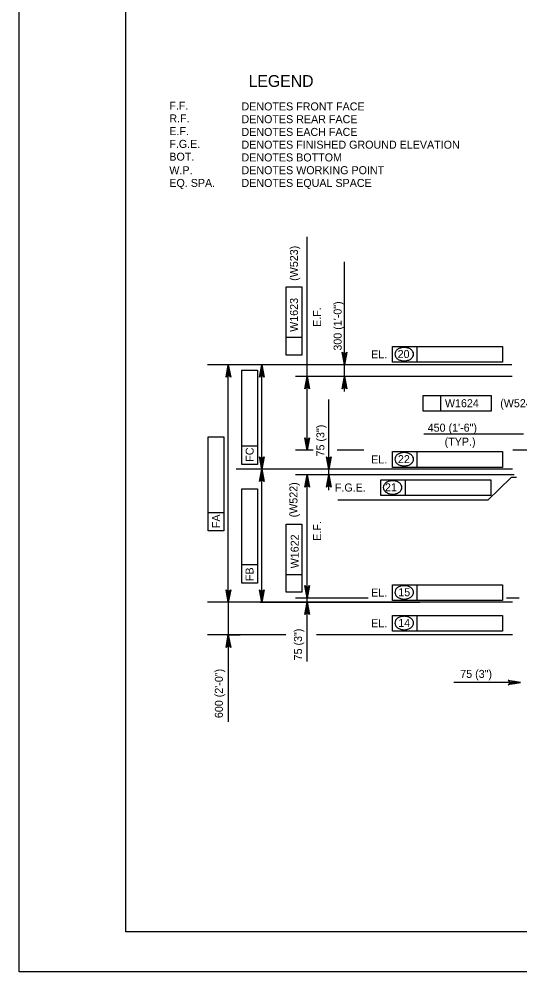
# Model space of a CAD drawing. Extents: x 634540 to 640306, y 296059 to 300275.
# Drawn here: x 638435.5 to 638623.2, y 296059.5 to 296416.6 of the extents above; entities that cross this region are included whole.
import ezdxf

# ---------------------------------------------------------------- set-up
doc = ezdxf.new("R2010")
doc.units = 0
for name, color, linetype in [('2', 7, 'Continuous'), ('3', 7, 'Continuous'), ('4', 7, 'Continuous'), ('PLT-BNDY', 7, 'Continuous')]:
    doc.layers.add(name, color=color, linetype=linetype)

msp = doc.modelspace()

# ---------------------------------------------------------------- linework, layer by layer
at = {"layer": '2'}
for p, q in [((638475.46, 296074.46), (638475.46, 296638.46)), ((639261.46, 296074.46), (638475.46, 296074.46))]:
    msp.add_line(p, q, dxfattribs=at)
at = {"layer": '3'}
for p, q in [((638624.51, 296260.98), (638587.22, 296260.98)), ((638621.91, 296244.82), (638619.95, 296244.82))]:
    msp.add_line(p, q, dxfattribs=at)
at = {"layer": '4'}
for p, q in [((638543.46, 296257.92), (638543.46, 296335.02)), ((638557.42, 296276.97), (638557.42, 296325.64)), ((638535.57, 296290.66), (638535.57, 296316.19)), ((638535.57, 296316.19), (638541.48, 296316.19)), ((638541.48, 296316.19), (638541.48, 296290.66)), ((638541.48, 296297.25), (638535.57, 296297.25)), ((638575.44, 296293.83), (638616.65, 296293.83)), ((638575.44, 296287.93), (638575.44, 296293.83)), ((638584.61, 296287.93), (638584.61, 296293.83)), ((638616.65, 296293.83), (638616.65, 296287.93)), ((638541.48, 296290.66), (638535.57, 296290.66)), ((638620.17, 296287.02), (638506.06, 296287.02)), ((638521.43, 296287.02), (638509.46, 296287.02)), ((638585.87, 296287.02), (638522.01, 296287.02)), ((638616.65, 296287.93), (638575.44, 296287.93)), ((638513.89, 296201.02), (638513.89, 296284.07)), ((638518.91, 296249.64), (638518.91, 296284.95)), ((638518.91, 296284.95), (638524.81, 296284.95)), ((638524.81, 296284.95), (638524.81, 296249.64)), ((638526.44, 296250.85), (638526.44, 296284.07)), ((638620.29, 296282.65), (638539.03, 296282.65)), ((638586.92, 296275.52), (638612.46, 296275.52)), ((638586.92, 296269.61), (638586.92, 296275.52)), ((638593.51, 296269.61), (638593.51, 296275.52)), ((638612.46, 296275.52), (638612.46, 296269.61)), ((638551.53, 296240.06), (638551.53, 296273.97)), ((638612.46, 296269.61), (638586.92, 296269.61)), ((638506.36, 296224.73), (638506.36, 296260.03)), ((638506.36, 296260.03), (638512.27, 296260.03)), ((638512.27, 296260.03), (638512.27, 296224.73)), ((638524.81, 296256.49), (638518.91, 296256.49)), ((638545.67, 296254.97), (638539.03, 296254.97)), ((638564.74, 296254.97), (638554.72, 296254.97)), ((638575.44, 296254.45), (638616.65, 296254.45)), ((638575.44, 296248.54), (638575.44, 296254.45)), ((638584.61, 296248.54), (638584.61, 296254.45)), ((638616.65, 296254.45), (638616.65, 296248.54)), ((638636.58, 296254.97), (638620.55, 296254.97)), ((638620.46, 296247.9), (638516.83, 296247.9)), ((638524.81, 296249.64), (638518.91, 296249.64)), ((638592.28, 296247.9), (638522.01, 296247.9)), ((638585.87, 296247.9), (638522.01, 296247.9)), ((638616.65, 296248.54), (638575.44, 296248.54)), ((638526.44, 296201.02), (638526.44, 296244.94)), ((638621.06, 296245.74), (638539.03, 296245.74)), ((638571.09, 296243.88), (638612.3, 296243.88)), ((638571.09, 296237.97), (638571.09, 296243.88)), ((638580.26, 296237.97), (638580.26, 296243.88)), ((638619.95, 296244.82), (638611.11, 296236.3)), ((638612.3, 296243.88), (638612.3, 296237.97)), ((638518.91, 296205.17), (638518.91, 296240.47)), ((638518.91, 296240.47), (638524.81, 296240.47)), ((638524.81, 296240.47), (638524.81, 296205.17)), ((638543.46, 296198.06), (638543.46, 296242.79)), ((638611.11, 296236.3), (638554.98, 296236.3)), ((638612.3, 296237.97), (638571.09, 296237.97)), ((638512.27, 296231.57), (638506.36, 296231.57)), ((638535.57, 296201.75), (638535.57, 296227.28)), ((638535.57, 296227.28), (638541.48, 296227.28)), ((638541.48, 296227.28), (638541.48, 296201.75)), ((638512.27, 296224.73), (638506.36, 296224.73)), ((638524.81, 296212.01), (638518.91, 296212.01)), ((638541.48, 296208.34), (638535.57, 296208.34)), ((638524.81, 296205.17), (638518.91, 296205.17)), ((638575.44, 296204.56), (638616.65, 296204.56)), ((638575.44, 296198.65), (638575.44, 296204.56)), ((638584.61, 296198.65), (638584.61, 296204.56)), ((638616.65, 296204.56), (638616.65, 296198.65)), ((638541.48, 296201.75), (638535.57, 296201.75)), ((638620.46, 296198.06), (638506.06, 296198.06)), ((638521.43, 296198.06), (638509.46, 296198.06)), ((638513.89, 296198.06), (638513.89, 296185.76)), ((638592.28, 296198.06), (638522.01, 296198.06)), ((638525.84, 296198.06), (638585.7, 296198.06)), ((638566.35, 296199.6), (638539.03, 296199.6)), ((638616.65, 296198.65), (638575.44, 296198.65)), ((638622.94, 296199.6), (638618.16, 296199.6)), ((638543.46, 296175.86), (638543.46, 296195.11)), ((638575.44, 296193.07), (638616.65, 296193.07)), ((638575.44, 296187.17), (638575.44, 296193.07)), ((638584.61, 296187.17), (638584.61, 296193.07)), ((638616.65, 296193.07), (638616.65, 296187.17)), ((638616.65, 296187.17), (638575.44, 296187.17)), ((638535.5, 296185.76), (638506.06, 296185.76)), ((638513.29, 296185.76), (638518.32, 296185.76)), ((638513.89, 296182.81), (638513.89, 296153.14)), ((638620.46, 296185.76), (638546.92, 296185.76)), ((638617.54, 296167.92), (638598.47, 296167.92)), ((638620.49, 296167.92), (638617.54, 296167.92))]:
    msp.add_line(p, q, dxfattribs=at)
for points in [[(638557.42, 296287.02), (638556.55, 296291.68), (638556.8, 296291.32), (638557.11, 296291.14), (638557.42, 296291.08), (638557.74, 296291.14), (638558.05, 296291.32), (638558.3, 296291.68), (638557.42, 296287.02), (638558.05, 296291.32), (638557.74, 296291.14), (638557.42, 296287.02), (638557.42, 296291.08), (638557.11, 296291.14), (638557.42, 296287.02), (638556.8, 296291.32)], [(638513.89, 296287.02), (638514.77, 296282.36), (638514.52, 296282.72), (638514.21, 296282.9), (638513.89, 296282.96), (638513.58, 296282.9), (638513.27, 296282.72), (638513.02, 296282.36), (638513.89, 296287.02), (638513.27, 296282.72), (638513.58, 296282.9), (638513.89, 296287.02), (638513.89, 296282.96), (638514.21, 296282.9), (638513.89, 296287.02), (638514.52, 296282.72)], [(638526.44, 296287.02), (638527.31, 296282.36), (638527.07, 296282.72), (638526.75, 296282.9), (638526.44, 296282.96), (638526.13, 296282.9), (638525.82, 296282.72), (638525.57, 296282.36), (638526.44, 296287.02), (638525.82, 296282.72), (638526.13, 296282.9), (638526.44, 296287.02), (638526.44, 296282.96), (638526.75, 296282.9), (638526.44, 296287.02), (638527.07, 296282.72)], [(638543.46, 296282.65), (638544.33, 296277.99), (638544.09, 296278.35), (638543.77, 296278.54), (638543.46, 296278.59), (638543.15, 296278.54), (638542.84, 296278.35), (638542.59, 296277.99), (638543.46, 296282.65), (638542.84, 296278.35), (638543.15, 296278.54), (638543.46, 296282.65), (638543.46, 296278.59), (638543.77, 296278.54), (638543.46, 296282.65), (638544.09, 296278.35)], [(638557.42, 296282.65), (638558.3, 296277.99), (638558.05, 296278.35), (638557.74, 296278.54), (638557.42, 296278.59), (638557.11, 296278.54), (638556.8, 296278.35), (638556.55, 296277.99), (638557.42, 296282.65), (638556.8, 296278.35), (638557.11, 296278.54), (638557.42, 296282.65), (638557.42, 296278.59), (638557.74, 296278.54), (638557.42, 296282.65), (638558.05, 296278.35)], [(638543.46, 296254.97), (638542.59, 296259.63), (638542.84, 296259.27), (638543.15, 296259.09), (638543.46, 296259.03), (638543.77, 296259.09), (638544.09, 296259.27), (638544.33, 296259.63), (638543.46, 296254.97), (638544.09, 296259.27), (638543.77, 296259.09), (638543.46, 296254.97), (638543.46, 296259.03), (638543.15, 296259.09), (638543.46, 296254.97), (638542.84, 296259.27)], [(638526.44, 296247.9), (638525.57, 296252.56), (638525.82, 296252.2), (638526.13, 296252.01), (638526.44, 296251.96), (638526.75, 296252.01), (638527.07, 296252.2), (638527.31, 296252.56), (638526.44, 296247.9), (638527.07, 296252.2), (638526.75, 296252.01), (638526.44, 296247.9), (638526.44, 296251.96), (638526.13, 296252.01), (638526.44, 296247.9), (638525.82, 296252.2)], [(638551.53, 296247.9), (638550.66, 296252.56), (638550.91, 296252.2), (638551.22, 296252.01), (638551.53, 296251.96), (638551.85, 296252.01), (638552.16, 296252.2), (638552.41, 296252.56), (638551.53, 296247.9), (638552.16, 296252.2), (638551.85, 296252.01), (638551.53, 296247.9), (638551.53, 296251.96), (638551.22, 296252.01), (638551.53, 296247.9), (638550.91, 296252.2)], [(638526.44, 296247.9), (638527.31, 296243.23), (638527.07, 296243.59), (638526.75, 296243.78), (638526.44, 296243.83), (638526.13, 296243.78), (638525.82, 296243.59), (638525.57, 296243.23), (638526.44, 296247.9), (638525.82, 296243.59), (638526.13, 296243.78), (638526.44, 296247.9), (638526.44, 296243.83), (638526.75, 296243.78), (638526.44, 296247.9), (638527.07, 296243.59)], [(638543.46, 296245.74), (638544.33, 296241.08), (638544.09, 296241.44), (638543.77, 296241.62), (638543.46, 296241.68), (638543.15, 296241.62), (638542.84, 296241.44), (638542.59, 296241.08), (638543.46, 296245.74), (638542.84, 296241.44), (638543.15, 296241.62), (638543.46, 296245.74), (638543.46, 296241.68), (638543.77, 296241.62), (638543.46, 296245.74), (638544.09, 296241.44)], [(638551.53, 296245.74), (638552.41, 296241.08), (638552.16, 296241.44), (638551.85, 296241.62), (638551.53, 296241.68), (638551.22, 296241.62), (638550.91, 296241.44), (638550.66, 296241.08), (638551.53, 296245.74), (638550.91, 296241.44), (638551.22, 296241.62), (638551.53, 296245.74), (638551.53, 296241.68), (638551.85, 296241.62), (638551.53, 296245.74), (638552.16, 296241.44)], [(638543.46, 296199.6), (638542.59, 296204.26), (638542.84, 296203.91), (638543.15, 296203.72), (638543.46, 296203.67), (638543.77, 296203.72), (638544.09, 296203.91), (638544.33, 296204.26), (638543.46, 296199.6), (638544.09, 296203.91), (638543.77, 296203.72), (638543.46, 296199.6), (638543.46, 296203.67), (638543.15, 296203.72), (638543.46, 296199.6), (638542.84, 296203.91)], [(638513.89, 296198.06), (638513.02, 296202.72), (638513.27, 296202.37), (638513.58, 296202.18), (638513.89, 296202.13), (638514.21, 296202.18), (638514.52, 296202.37), (638514.77, 296202.72), (638513.89, 296198.06), (638514.52, 296202.37), (638514.21, 296202.18), (638513.89, 296198.06), (638513.89, 296202.13), (638513.58, 296202.18), (638513.89, 296198.06), (638513.27, 296202.37)], [(638526.44, 296198.06), (638525.57, 296202.72), (638525.82, 296202.37), (638526.13, 296202.18), (638526.44, 296202.13), (638526.75, 296202.18), (638527.07, 296202.37), (638527.31, 296202.72), (638526.44, 296198.06), (638527.07, 296202.37), (638526.75, 296202.18), (638526.44, 296198.06), (638526.44, 296202.13), (638526.13, 296202.18), (638526.44, 296198.06), (638525.82, 296202.37)], [(638543.46, 296198.06), (638544.33, 296193.4), (638544.09, 296193.76), (638543.77, 296193.95), (638543.46, 296194), (638543.15, 296193.95), (638542.84, 296193.76), (638542.59, 296193.4), (638543.46, 296198.06), (638542.84, 296193.76), (638543.15, 296193.95), (638543.46, 296198.06), (638543.46, 296194), (638543.77, 296193.95), (638543.46, 296198.06), (638544.09, 296193.76)], [(638513.89, 296185.76), (638514.77, 296181.1), (638514.52, 296181.46), (638514.21, 296181.64), (638513.89, 296181.7), (638513.58, 296181.64), (638513.27, 296181.46), (638513.02, 296181.1), (638513.89, 296185.76), (638513.27, 296181.46), (638513.58, 296181.64), (638513.89, 296185.76), (638513.89, 296181.7), (638514.21, 296181.64), (638513.89, 296185.76), (638514.52, 296181.46)], [(638623.45, 296167.92), (638618.79, 296167.04), (638619.15, 296167.29), (638619.33, 296167.6), (638619.39, 296167.92), (638619.33, 296168.23), (638619.15, 296168.54), (638618.79, 296168.79), (638623.45, 296167.92), (638619.15, 296168.54), (638619.33, 296168.23), (638623.45, 296167.92), (638619.39, 296167.92), (638619.33, 296167.6), (638623.45, 296167.92), (638619.15, 296167.29)]]:
    msp.add_lwpolyline(points, dxfattribs=at)
for points in [[(638556.93, 296289.97), (638557.92, 296289.97), (638557.42, 296287.02)], [(638513.4, 296284.07), (638514.38, 296284.07), (638513.89, 296287.02)], [(638525.95, 296284.07), (638526.93, 296284.07), (638526.44, 296287.02)], [(638542.97, 296279.7), (638543.95, 296279.7), (638543.46, 296282.65)], [(638556.93, 296279.7), (638557.92, 296279.7), (638557.42, 296282.65)], [(638542.97, 296257.92), (638543.95, 296257.92), (638543.46, 296254.97)], [(638525.95, 296250.85), (638526.93, 296250.85), (638526.44, 296247.9)], [(638551.04, 296250.85), (638552.03, 296250.85), (638551.53, 296247.9)], [(638525.95, 296244.94), (638526.93, 296244.94), (638526.44, 296247.9)], [(638542.97, 296242.79), (638543.95, 296242.79), (638543.46, 296245.74)], [(638551.04, 296242.79), (638552.03, 296242.79), (638551.53, 296245.74)], [(638513.4, 296201.02), (638514.38, 296201.02), (638513.89, 296198.06)], [(638525.95, 296201.02), (638526.93, 296201.02), (638526.44, 296198.06)], [(638542.97, 296202.56), (638543.95, 296202.56), (638543.46, 296199.6)], [(638542.97, 296195.11), (638543.95, 296195.11), (638543.46, 296198.06)], [(638513.4, 296182.81), (638514.38, 296182.81), (638513.89, 296185.76)], [(638620.49, 296168.41), (638620.49, 296167.42), (638623.45, 296167.92)]]:
    msp.add_lwpolyline(points, close=True, dxfattribs=at)
for centre, radius, start, end in [((638579.47, 296289.79), 3.66, 106.5358, 125.6316), ((638579.81, 296288.63), 4.87, 90, 106.5358), ((638579.81, 296288.63), 4.87, 73.4642, 90), ((638580.16, 296289.79), 3.66, 54.3684, 73.4642), ((638578.14, 296290.99), 1.83, 149.9767, 180), ((638578.14, 296290.99), 1.83, 180, 210.0233), ((638578.94, 296290.52), 2.76, 125.6316, 149.9767), ((638578.94, 296291.45), 2.76, 210.0233, 234.3684), ((638580.68, 296290.52), 2.76, 30.0233, 54.3684), ((638580.68, 296291.45), 2.76, 305.6316, 329.9767), ((638581.49, 296290.99), 1.83, 0, 30.0233), ((638581.49, 296290.99), 1.83, 329.9767, 0), ((638579.47, 296292.19), 3.66, 234.3684, 253.4642), ((638579.81, 296293.35), 4.87, 253.4642, 270), ((638579.81, 296293.35), 4.87, 270, 286.5358), ((638580.16, 296292.19), 3.66, 286.5358, 305.6316), ((638579.47, 296250.4), 3.66, 106.5358, 125.6316), ((638579.81, 296249.24), 4.87, 90, 106.5358), ((638579.81, 296249.24), 4.87, 73.4642, 90), ((638580.16, 296250.4), 3.66, 54.3684, 73.4642), ((638578.14, 296251.6), 1.83, 149.9767, 180), ((638578.14, 296251.6), 1.83, 180, 210.0233), ((638578.94, 296251.14), 2.76, 125.6316, 149.9767), ((638578.94, 296252.07), 2.76, 210.0233, 234.3684), ((638580.68, 296251.14), 2.76, 30.0233, 54.3684), ((638580.68, 296252.07), 2.76, 305.6316, 329.9767), ((638581.49, 296251.6), 1.83, 0, 30.0233), ((638581.49, 296251.6), 1.83, 329.9767, 0), ((638579.47, 296252.8), 3.66, 234.3684, 253.4642), ((638579.81, 296253.96), 4.87, 253.4642, 270), ((638579.81, 296253.96), 4.87, 270, 286.5358), ((638580.16, 296252.8), 3.66, 286.5358, 305.6316), ((638575.12, 296239.83), 3.66, 106.5358, 125.6316), ((638575.47, 296238.67), 4.87, 90, 106.5358), ((638575.47, 296238.67), 4.87, 73.4642, 90), ((638575.81, 296239.83), 3.66, 54.3684, 73.4642), ((638573.79, 296241.03), 1.83, 149.9767, 180), ((638573.79, 296241.03), 1.83, 180, 210.0233), ((638574.6, 296240.57), 2.76, 125.6316, 149.9767), ((638574.6, 296241.5), 2.76, 210.0233, 234.3684), ((638576.34, 296240.57), 2.76, 30.0233, 54.3684), ((638576.34, 296241.5), 2.76, 305.6316, 329.9767), ((638577.14, 296241.03), 1.83, 0, 30.0233), ((638577.14, 296241.03), 1.83, 329.9767, 0), ((638575.12, 296242.24), 3.66, 234.3684, 253.4642), ((638575.47, 296243.4), 4.87, 253.4642, 270), ((638575.47, 296243.4), 4.87, 270, 286.5358), ((638575.81, 296242.24), 3.66, 286.5358, 305.6316), ((638579.47, 296200.51), 3.66, 106.5358, 125.6316), ((638579.81, 296199.35), 4.87, 90, 106.5358), ((638579.81, 296199.35), 4.87, 73.4642, 90), ((638580.16, 296200.51), 3.66, 54.3684, 73.4642), ((638578.14, 296201.71), 1.83, 149.9767, 180), ((638578.14, 296201.71), 1.83, 180, 210.0233), ((638578.94, 296201.25), 2.76, 125.6316, 149.9767), ((638578.94, 296202.18), 2.76, 210.0233, 234.3684), ((638580.68, 296201.25), 2.76, 30.0233, 54.3684), ((638580.68, 296202.18), 2.76, 305.6316, 329.9767), ((638581.49, 296201.71), 1.83, 0, 30.0233), ((638581.49, 296201.71), 1.83, 329.9767, 0), ((638579.47, 296202.91), 3.66, 234.3684, 253.4642), ((638579.81, 296204.07), 4.87, 253.4642, 270), ((638579.81, 296204.07), 4.87, 270, 286.5358), ((638580.16, 296202.91), 3.66, 286.5358, 305.6316), ((638578.14, 296190.23), 1.83, 149.9767, 180), ((638578.14, 296190.23), 1.83, 180, 210.0233), ((638578.94, 296189.76), 2.76, 125.6316, 149.9767), ((638579.47, 296189.03), 3.66, 106.5358, 125.6316), ((638579.81, 296187.87), 4.87, 90, 106.5358), ((638579.81, 296187.87), 4.87, 73.4642, 90), ((638580.16, 296189.03), 3.66, 54.3684, 73.4642), ((638580.68, 296189.76), 2.76, 30.0233, 54.3684), ((638581.49, 296190.23), 1.83, 0, 30.0233), ((638581.49, 296190.23), 1.83, 329.9767, 0), ((638578.94, 296190.69), 2.76, 210.0233, 234.3684), ((638579.47, 296191.43), 3.66, 234.3684, 253.4642), ((638579.81, 296192.59), 4.87, 253.4642, 270), ((638579.81, 296192.59), 4.87, 270, 286.5358), ((638580.16, 296191.43), 3.66, 286.5358, 305.6316), ((638580.68, 296190.69), 2.76, 305.6316, 329.9767)]:
    msp.add_arc(centre, radius, start, end, dxfattribs=at)
at = {"layer": 'PLT-BNDY'}
msp.add_lwpolyline([(638435.46, 296653.46), (639276.46, 296653.46), (639276.46, 296059.46), (638435.46, 296059.46)], close=True, dxfattribs=at)

# ---------------------------------------------------------------- texts
at = {"layer": '3'}
for s, height, p in [('450 (1\'-6")', 3.0001, (638588.62, 296261.94)), ('(TYP.)', 3, (638594.97, 296256.69))]:
    msp.add_text(s, height=height, dxfattribs=at).set_placement(p)
at = {"layer": '4'}
for s, height, p in [('LEGEND', 4.429, (638521.48, 296391.15)), ('F.F.', 3, (638491.78, 296382.63)), ('DENOTES FRONT FACE', 3.0001, (638518.82, 296382.34)), ('R.F.', 3, (638491.78, 296377.85)), ('DENOTES REAR FACE', 3.0001, (638518.82, 296377.56)), ('E.F.', 3, (638491.78, 296373.07)), ('DENOTES EACH FACE', 3.0001, (638518.82, 296372.78)), ('F.G.E.', 3, (638491.78, 296368.29)), ('DENOTES FINISHED GROUND ELEVATION', 3.0001, (638518.82, 296368)), ('BOT.', 3, (638491.78, 296363.51)), ('DENOTES BOTTOM', 3.0001, (638518.82, 296363.22)), ('W.P.', 3, (638491.78, 296358.44)), ('DENOTES WORKING POINT', 3.0001, (638518.82, 296358.44)), ('EQ. SPA.', 3, (638491.78, 296353.66)), ('DENOTES EQUAL SPACE', 3.0001, (638518.82, 296353.66)), ('EL.', 3, (638567.41, 296289.41)), ('20', 3, (638577.35, 296289.53)), ('W1624', 3, (638595.07, 296271.1)), ('(W524)', 3, (638615.8, 296271.1)), ('EL.', 3, (638567.41, 296250.03)), ('22', 3, (638577.46, 296250.14)), ('F.G.E.', 3, (638553.82, 296239.51)), ('21', 3, (638572.59, 296239.57)), ('EL.', 3, (638567.41, 296200.14)), ('15', 3, (638577.6, 296200.25)), ('EL.', 3, (638567.41, 296188.65)), ('14', 3, (638577.57, 296188.77)), ('75 (3")', 3, (638600.82, 296169.66))]:
    msp.add_text(s, height=height, dxfattribs=at).set_placement(p)
for s, height, p in [('(W523)', 3, (638539.99, 296318.46)), ('W1623', 3, (638539.99, 296299.35)), ('E.F.', 3, (638548.65, 296301.21)), ('300 (1\'-0")', 3.0001, (638556.36, 296292.31)), ('75 (3")', 3, (638549.9, 296252.65)), ('FC', 3, (638523.39, 296250.67)), ('(W522)', 3, (638539.8, 296229.83)), ('FA', 3, (638510.78, 296225.79)), ('E.F.', 3, (638548.68, 296221.06)), ('W1622', 3, (638540.27, 296210.72)), ('FB', 3, (638523.33, 296205.94)), ('75 (3")', 3, (638541.51, 296176.22)), ('600 (2\'-0")', 3.0001, (638511.85, 296154.59))]:
    msp.add_text(s, height=height, rotation=90, dxfattribs=at).set_placement(p)

doc.saveas('drawing.dxf')
